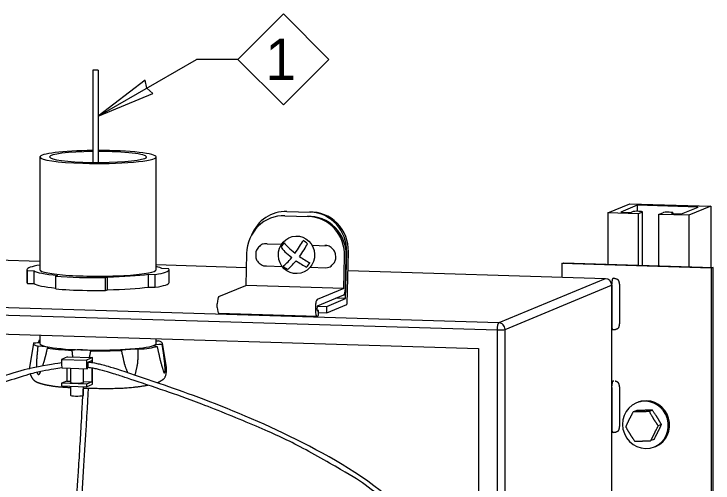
# Model space of a CAD drawing. Extents: x 99862 to 104211, y 98939 to 102076.
# Drawn here: x 102473.8 to 102744.3, y 101168.9 to 101350.4 of the extents above; entities that cross this region are included whole.
import ezdxf

# ---------------------------------------------------------------- set-up
doc = ezdxf.new("R2010")
doc.units = 0
for name, color, linetype in [('Level 1', 7, 'Continuous'), ('Level 11', 7, 'Continuous'), ('Level 15', 7, 'Continuous'), ('Level 17', 7, 'Continuous'), ('Level 18', 7, 'Continuous'), ('Level 19', 7, 'Continuous'), ('Level 20', 7, 'Continuous'), ('Level 22', 7, 'Continuous'), ('Level 30', 7, 'Continuous'), ('Level 4', 7, 'Continuous'), ('Level 5', 7, 'Continuous'), ('Level 6', 7, 'Continuous'), ('Level 8', 7, 'Continuous'), ('Level 9', 7, 'Continuous')]:
    doc.layers.add(name, color=color, linetype=linetype)

msp = doc.modelspace()

# ---------------------------------------------------------------- linework, layer by layer
at = {"layer": 'Level 1'}
for p, q in [((102483.78, 101254.68), (102435.76, 101256.14)), ((102563.61, 101252.25), (102528.78, 101253.31)), ((102702.71, 101248.01), (102602.99, 101251.05)), ((102702.63, 101248), (102661.4, 101230.93)), ((102663.81, 101228.38), (102705.04, 101245.44)), ((102705.04, 101245.44), (102705.04, 101150.38)), ((102661.4, 101230.93), (102318.77, 101241.36)), ((102318.11, 101238.61), (102660.74, 101228.18)), ((102325.59, 101230.93), (102653.5, 101220.95)), ((102660.74, 101228.18), (102660.74, 100794.54)), ((102663.81, 100794.74), (102663.81, 101228.38)), ((102653.5, 101220.95), (102653.5, 100802.46))]:
    msp.add_line(p, q, dxfattribs=at)
msp.add_arc((102702.63, 101245.51), 2.5, 360, 88.2563, dxfattribs=at)
for centre, major_axis, ratio, start_param, end_param in [((102702.63, 101245.51), (0.08, 2.5), 0.260126, 0, 0.1165), ((102702.63, 101245.51), (-2.5, 0), 0.112235, 2.876726, 3.141593), ((102661.4, 101228.45), (0.08, 2.5), 0.260126, 0.1165, 1.687296), ((102661.4, 101228.45), (0.96, -2.31), 0.959029, 1.163464, 2.734261), ((102661.4, 101228.45), (2.5, 0), 0.112235, 4.447522, 6.018319)]:
    msp.add_ellipse(centre, major_axis=major_axis, ratio=ratio, start_param=start_param, end_param=end_param, dxfattribs=at)
at = {"layer": 'Level 11'}
msp.add_ellipse((102583.09, 101257.22), major_axis=(0.3, -7.27), ratio=0.965403, dxfattribs=at)
for centre, major_axis, ratio, start_param, end_param in [((102582.66, 101257.2), (0.27, -6.47), 0.965403, 3.859694, 4.191654), ((102584.38, 101258.1), (6.19, -4.51), 0.165581, 3.52142, 4.536345), ((102581.75, 101258.92), (4.51, 6.19), 0.165581, 4.664043, 5.491937), ((102582.65, 101257.2), (6.47, 0.27), 0.965403, 0.715535, 1.047495), ((102583.14, 101256.39), (-6.19, 4.5), 0.165581, 0.380026, 1.385852), ((102583.46, 101257.68), (-4.5, -6.19), 0.165581, 1.520706, 2.350146), ((102584.38, 101258.1), (6.19, -4.51), 0.165581, 4.812672, 5.491937), ((102581.75, 101258.92), (4.51, 6.19), 0.165581, 3.52142, 4.383143), ((102583.46, 101257.68), (-4.5, -6.19), 0.165581, 0.380026, 1.239194), ((102583.14, 101256.39), (-6.19, 4.5), 0.165581, 1.662256, 2.350146), ((102582.66, 101257.2), (0.27, -6.47), 0.965403, 0.715535, 1.047495), ((102582.65, 101257.2), (6.47, 0.27), 0.965403, 3.859694, 4.191654)]:
    msp.add_ellipse(centre, major_axis=major_axis, ratio=ratio, start_param=start_param, end_param=end_param, dxfattribs=at)
at = {"layer": 'Level 15'}
for p in [(102506.28, 101310.85), (102560.45, 101332.88)]:
    msp.add_line(p, (102544.45, 101332.88), dxfattribs=at)
msp.add_lwpolyline([(102506.28, 101310.85), (102527.55, 101319.68), (102525.14, 101321.73), (102524.56, 101324.85)], close=True, dxfattribs=at)
at = {"layer": 'Level 17'}
for p, q in [((102703.63, 101273.48), (102712.14, 101277)), ((102715, 101276.44), (102708.62, 101273.8)), ((102712.14, 101277), (102743.51, 101276.05)), ((102715, 101276.44), (102715, 101274.07)), ((102738.52, 101275.73), (102715, 101276.44)), ((102732.14, 101273.09), (102738.52, 101275.73)), ((102743.51, 101276.05), (102735, 101272.53)), ((102743.51, 101276.05), (102743.51, 101252.39)), ((102703.63, 101273.48), (102703.63, 101253.61)), ((102715.4, 101273.12), (102703.63, 101273.48)), ((102708.62, 101273.8), (102712.54, 101273.68)), ((102712.54, 101273.68), (102713.07, 101273.9)), ((102716.99, 101273.79), (102715.4, 101273.12)), ((102715.4, 101273.12), (102715.4, 101253.25)), ((102715.55, 101274.06), (102715.58, 101274.06)), ((102717.07, 101253.2), (102717.07, 101273.84)), ((102723.24, 101272.88), (102724.84, 101273.55)), ((102723.24, 101272.88), (102723.24, 101253.01)), ((102735, 101272.53), (102723.24, 101272.88)), ((102728.76, 101273.43), (102728.22, 101273.21)), ((102728.22, 101273.21), (102732.14, 101273.09)), ((102728.83, 101273.19), (102728.83, 101273.49)), ((102735, 101272.53), (102735, 101252.65))]:
    msp.add_line(p, q, dxfattribs=at)
for centre, start_param, end_param in [((102715.02, 101273.85), 1.30593, 2.876726), ((102715.05, 101273.84), 0, 1.30593), ((102715.05, 101273.84), 6.018319, 6.283185), ((102726.78, 101273.49), 1.30593, 2.876726), ((102726.81, 101273.49), 6.283185, 7.589115), ((102726.81, 101273.49), 6.018319, 6.283185)]:
    msp.add_ellipse(centre, major_axis=(2.01, 0), ratio=0.112235, start_param=start_param, end_param=end_param, dxfattribs=at)
at = {"layer": 'Level 18'}
for p, q in [((102685.75, 101253.86), (102685.75, 101248.51)), ((102743.65, 101252.1), (102685.75, 101253.86)), ((102744.31, 101045.46), (102744.31, 101252.37))]:
    msp.add_line(p, q, dxfattribs=at)
msp.add_lwpolyline([(102685.75, 101253.86), (102686.4, 101254.13), (102744.31, 101252.37), (102743.65, 101252.1), (102743.65, 101045.48)], dxfattribs=at)
at = {"layer": 'Level 19'}
for p, q in [((102715.12, 101200.12), (102714.63, 101199.92)), ((102714.58, 101196.93), (102713.35, 101196.43)), ((102720.89, 101197.11), (102719.67, 101196.6)), ((102724.35, 101191.56), (102723.13, 101191.05)), ((102721.51, 101185.83), (102720.28, 101185.33)), ((102721.66, 101182.93), (102722.15, 101183.13))]:
    msp.add_line(p, q, dxfattribs=at)
for centre, start_param, end_param in [((102718.15, 101191.43), 3.141593, 6.283185), ((102718.15, 101191.43), 2.914664, 3.141593), ((102718.63, 101191.63), 2.914664, 3.141593), ((102718.15, 101191.43), 6.283185, 9.197849), ((102718.63, 101191.63), 6.283185, 9.197849)]:
    msp.add_ellipse(centre, major_axis=(3.52, -8.5), ratio=0.959029, start_param=start_param, end_param=end_param, dxfattribs=at)
for points in [[(102720.89, 101197.11), (102718.87, 101197.09), (102716.77, 101197.03), (102714.58, 101196.93)], [(102724.35, 101191.56), (102723.41, 101193.24), (102722.38, 101194.89), (102720.89, 101197.11)], [(102713.35, 101196.43), (102712.32, 101194.48), (102711.37, 101192.58), (102710.51, 101190.7)], [(102719.67, 101196.6), (102717.48, 101196.51), (102715.37, 101196.45), (102713.35, 101196.43)], [(102723.13, 101191.05), (102722.03, 101192.67), (102720.99, 101194.31), (102719.67, 101196.6)], [(102721.51, 101185.83), (102722.54, 101187.78), (102723.49, 101189.69), (102724.35, 101191.56)], [(102710.51, 101190.7), (102711.59, 101188.82), (102712.72, 101186.96), (102713.97, 101185.15)], [(102720.28, 101185.33), (102721.15, 101187.2), (102722.1, 101189.11), (102723.13, 101191.05)], [(102713.97, 101185.15), (102715.99, 101185.17), (102718.09, 101185.23), (102720.28, 101185.33)]]:
    msp.add_open_spline(points, degree=2, dxfattribs=at)
at = {"layer": 'Level 20'}
msp.add_lwpolyline([(102578.01, 101350.44), (102595.56, 101332.88), (102578.01, 101315.33), (102560.45, 101332.88)], close=True, dxfattribs=at)
at = {"layer": 'Level 22'}
for p, q in [((102705.1, 101245.47), (102705.1, 101230.32)), ((102708.1, 101245.88), (102708.1, 101230.49)), ((102705.56, 101228.32), (102705.86, 101228.28)), ((102705.72, 101208.45), (102705.7, 101208.45)), ((102705.72, 101208.45), (102705.87, 101208.44)), ((102705.1, 101205.95), (102705.1, 101190.57)), ((102708.1, 101206.13), (102708.1, 101190.75)), ((102705.63, 101188.56), (102705.84, 101188.55))]:
    msp.add_line(p, q, dxfattribs=at)
for points in [[(102705.86, 101228.28), (102706.05, 101228.29), (102706.56, 101228.39)], [(102705.84, 101188.55), (102706.03, 101188.56), (102706.54, 101188.66)]]:
    msp.add_lwpolyline(points, dxfattribs=at)
msp.add_ellipse((102705.83, 101208.46), major_axis=(0.129, 0), ratio=0.112235, start_param=3.805799, end_param=5.089246, dxfattribs=at)
for points in [[(102705.7, 101248.19), (102705.41, 101248.03), (102705.22, 101247.41), (102705.11, 101245.84)], [(102708.1, 101245.88), (102708.04, 101247.02), (102707.47, 101247.77), (102705.7, 101248.19)], [(102705.1, 101230.32), (102705.12, 101229.18), (102705.27, 101228.51), (102705.56, 101228.32)], [(102706.56, 101228.39), (102707.54, 101228.73), (102708.06, 101229.42), (102708.1, 101230.49)], [(102705.7, 101208.45), (102705.4, 101208.28), (102705.21, 101207.62), (102705.12, 101206.5)], [(102708.1, 101206.13), (102708.04, 101207.28), (102707.47, 101208.02), (102706.4, 101208.37)], [(102705.1, 101190.57), (102705.12, 101189.43), (102705.27, 101188.77), (102705.56, 101188.57)], [(102706.56, 101188.65), (102707.54, 101188.98), (102708.06, 101189.67), (102708.1, 101190.75)]]:
    msp.add_open_spline(points, degree=2, dxfattribs=at)
at = {"layer": 'Level 30'}
msp.add_line((102506.28, 101328.68), (102504.28, 101328.68), dxfattribs=at)
for points, degree in [([(102504.28, 101328.68), (102504.28, 101327.89), (102504.28, 101327.09), (102504.28, 101293.02)], 2), ([(102506.28, 101328.68), (102506.28, 101327.92), (102506.28, 101327.15), (102506.28, 101293.01)], 2), ([(102653.5, 101080.61), (102648.82, 101143.1), (102596.56, 101184.64), (102512.98, 101213.37), (102506.37, 101215.18), (102502.55, 101215.62), (102502.45, 101215.64)], 3), ([(102492.15, 101215.46), (102490.81, 101215.29), (102482.9, 101214.1), (102460.41, 101208.52), (102393.4, 101170.91), (102377.25, 101084.36), (102372.86, 101072.92), (102370.82, 101069.79), (102370.54, 101069.4)], 3), ([(102492.38, 101213.47), (102491.09, 101213.31), (102489.67, 101213.1), (102484.6, 101212.21), (102480.39, 101211.29), (102469.68, 101207.9), (102463.18, 101205.42), (102447.09, 101197.96), (102437.56, 101193), (102419.16, 101179.88), (102410.3, 101171.73), (102400.16, 101156.6), (102397.28, 101151.02), (102392.33, 101139.44), (102390.27, 101133.43), (102386.76, 101121.61), (102385.31, 101115.8), (102382.84, 101104.99), (102381.81, 101099.99), (102379.02, 101087.14), (102377.57, 101081.49), (102375.73, 101075.59), (102375.17, 101074.04), (102374.11, 101071.5), (102373.6, 101070.51), (102372.66, 101068.93), (102372.22, 101068.27), (102371.74, 101067.68)], 3), ([(102652.41, 101059.13), (102651.5, 101080.89), (102649.81, 101096.71), (102643.91, 101122.9), (102639.7, 101133.26), (102629.63, 101150.15), (102623.77, 101156.69), (102611.07, 101167.56), (102604.24, 101171.89), (102583.43, 101183.84), (102569.35, 101190.28), (102544.15, 101200.52), (102533.03, 101204.31), (102517.07, 101209.68), (102512.28, 101211.24), (102507.45, 101212.64), (102506.24, 101212.95), (102504.21, 101213.38), (102503.39, 101213.51), (102502.46, 101213.62), (102502.41, 101213.63), (102502.36, 101213.63)], 3), ([(102502.44, 101205.65), (102501.86, 101194.2), (102498.75, 101142.75), (102493.68, 101073.03), (102493.68, 101042.56), (102502.95, 101036.94), (102508.51, 101035.84)], 3), ([(102500.29, 101202.72), (102499.91, 101195.44), (102499.52, 101188.73), (102498.94, 101179.16), (102498.75, 101176.05), (102498.36, 101169.93), (102497.79, 101160.9), (102497.24, 101152.33), (102495.44, 101124.86), (102494.17, 101106.31), (102493.07, 101087.93), (102492.88, 101084.5), (102492.55, 101078.11), (102492.41, 101075.16), (102492.11, 101066.96), (102492.05, 101062.36), (102492.32, 101054.5), (102492.66, 101051.24), (102493.58, 101047.04), (102493.96, 101045.76), (102494.89, 101043.4), (102495.44, 101042.31), (102497.35, 101039.36), (102498.96, 101037.8), (102502.69, 101035.44), (102504.79, 101034.64), (102507.43, 101034.02), (102507.8, 101033.94), (102508.18, 101033.86)], 3)]:
    msp.add_open_spline(points, degree=degree, dxfattribs=at)
at = {"layer": 'Level 4'}
for p, q in [((102483.78, 101295.11), (102483.78, 101251.49)), ((102528.78, 101251.49), (102528.78, 101295.11)), ((102478.78, 101251.49), (102478.78, 101246.52)), ((102478.94, 101251.16), (102481.55, 101251.08)), ((102478.94, 101246.19), (102478.94, 101251.16)), ((102481.55, 101246.11), (102481.55, 101251.08)), ((102533.63, 101251.82), (102531.02, 101251.9)), ((102533.78, 101246.52), (102533.78, 101251.49)), ((102490.63, 101249.3), (102489.93, 101249.01)), ((102489.93, 101244.04), (102489.93, 101249.01)), ((102509.23, 101248.42), (102509.94, 101248.71)), ((102509.23, 101243.45), (102509.23, 101248.42)), ((102509.94, 101243.75), (102509.94, 101248.71)), ((102525.78, 101249.73), (102528.39, 101249.65)), ((102525.78, 101244.77), (102525.78, 101249.73)), ((102528.39, 101244.69), (102528.39, 101249.65)), ((102478.94, 101246.19), (102481.55, 101246.11)), ((102509.23, 101243.45), (102509.94, 101243.75)), ((102525.78, 101244.77), (102528.39, 101244.69)), ((102483.78, 101226.11), (102483.78, 101222.89)), ((102528.78, 101222.89), (102528.78, 101224.74))]:
    msp.add_line(p, q, dxfattribs=at)
for centre, major_axis, start_param, end_param in [((102506.28, 101295.11), (22.5, 0), 1.659816, 3.141593), ((102506.28, 101295.11), (-18.75, 0), 4.819275, 6.283185), ((102506.28, 101295.11), (22.5, 0), 0, 1.570808), ((102506.28, 101295.11), (-18.75, 0), 3.141593, 4.712403), ((102506.28, 101295.11), (22.5, 0), 3.141593, 4.447522), ((102506.28, 101295.11), (-18.75, 0), 6.283185, 9.159911), ((102506.28, 101295.11), (22.5, 0), 4.447522, 6.283185), ((102506.28, 101295.11), (-18.75, 0), 2.876726, 3.141593), ((102506.28, 101251.49), (-27.5, 0), 5.670631, 6.283185), ((102506.28, 101251.49), (-27.5, 0), 0, 0.107302), ((102506.28, 101251.49), (-25, 0), 0.14665, 0.894413), ((102506.28, 101251.49), (-22.5, 0), 0, 3.141593), ((102506.28, 101251.49), (-27.5, 0), 2.504558, 3.141593), ((102506.28, 101251.49), (-25, 0), 3.288243, 3.592619), ((102506.28, 101251.49), (-27.5, 0), 3.141593, 3.248895), ((102506.28, 101251.49), (-27.5, 0), 0.933761, 1.678098), ((102506.28, 101251.49), (-25, 0), 1.717447, 2.465209), ((102506.28, 101246.52), (-27.5, 0), 0, 0.107302), ((102506.28, 101246.52), (-25, 0), 0.14665, 0.857545), ((102506.28, 101246.52), (-27.5, 0), 2.504558, 3.141593), ((102506.28, 101246.52), (-27.5, 0), 0.933761, 1.155187), ((102506.28, 101246.52), (-27.5, 0), 1.155187, 1.678098), ((102506.28, 101246.52), (-25, 0), 1.717447, 2.465209), ((102506.28, 101222.89), (22.5, 0), 3.141593, 4.712389), ((102506.28, 101222.89), (22.5, 0), 4.712389, 6.283185)]:
    msp.add_ellipse(centre, major_axis=major_axis, ratio=0.112235, start_param=start_param, end_param=end_param, dxfattribs=at)
at = {"layer": 'Level 5'}
for p, q in [((102483.43, 101224.03), (102483.29, 101223.38)), ((102481.29, 101222.94), (102479.76, 101213.83)), ((102532.81, 101213.83), (102531.28, 101222.94)), ((102484.86, 101214.24), (102485.04, 101214.71)), ((102483.86, 101211.53), (102484.04, 101212.02))]:
    msp.add_line(p, q, dxfattribs=at)
msp.add_lwpolyline([(102531.39, 101212.81), (102531.53, 101212.4), (102531.53, 101212.39)], dxfattribs=at)
for centre, major_axis, ratio, start_param, end_param in [((102506.28, 101222.89), (-25, 0), 0.112235, 5.832158, 5.865849), ((102479.1, 101223.72), (5.29, -0.02), 0.106412, 0.484477, 0.612936), ((102530.72, 101224.46), (-5.24, -0.03), 0.108666, 1.191344, 1.356306), ((102506.28, 101222.89), (-25, 0), 0.112235, 3.160419, 3.509654), ((102506.28, 101222.89), (-25, 0), 0.112235, 6.264359, 6.651247), ((102506.28, 101222.89), (-25, 0), 0.112235, 6.170789, 6.264359), ((102479.1, 101223.72), (5.29, -0.02), 0.106412, 5.171338, 5.799417), ((102481.85, 101221.32), (5.24, 0.03), 0.108666, 6.248955, 7.639491), ((102481.85, 101221.32), (5.24, 0.03), 0.108666, 5.914708, 6.248955), ((102506.28, 101222.89), (-25, 0), 0.112235, 0.673002, 1.15346), ((102506.28, 101222.89), (-25, 0), 0.112235, 2.243798, 2.724256), ((102533.47, 101222.06), (-5.29, 0.02), 0.106412, 5.171338, 6.320463), ((102533.47, 101222.06), (-5.29, 0.02), 0.106412, 0.037278, 0.612936), ((102506.28, 101222.89), (-25, 0), 0.112235, 3.029196, 3.160419), ((102498.91, 101219.84), (-5.02, -0.02), 0.11826, 3.56882, 5.293603), ((102506.28, 101222.89), (-25, 0), 0.112235, 1.4584, 1.938858), ((102520.29, 101220.15), (-5.08, 0.03), 0.11559, 4.398046, 6.122829), ((102506.28, 101208.32), (23.4, 0), 0.112235, 3.465018, 3.516191)]:
    msp.add_ellipse(centre, major_axis=major_axis, ratio=ratio, start_param=start_param, end_param=end_param, dxfattribs=at)
for points in [[(102482.96, 101221.88), (102482.74, 101219.15), (102482.46, 101216.39), (102482.45, 101213.71)], [(102485.04, 101214.71), (102485.68, 101216.81), (102486.22, 101218.97), (102486.73, 101221.14)], [(102529.14, 101221.75), (102529.84, 101218.72), (102530.53, 101215.6), (102531.39, 101212.81)], [(102532.29, 101213.03), (102532.02, 101216.25), (102531.6, 101219.41), (102531.13, 101222.58)], [(102496.15, 101220.33), (102496.24, 101219.46), (102496.33, 101218.58), (102496.42, 101217.71)], [(102502.99, 101217.51), (102503.17, 101218.37), (102503.33, 101219.24), (102503.48, 101220.1)], [(102515.28, 101220.27), (102515.98, 101217.32), (102516.59, 101214.3), (102517.8, 101211.52)], [(102520.59, 101210.62), (102521.6, 101214.34), (102521.82, 101217.51), (102521.87, 101220.7)], [(102479.76, 101213.85), (102479.71, 101213.57), (102479.68, 101213.29), (102479.67, 101213.02)], [(102529.15, 101207.72), (102530.66, 101208.38), (102532.84, 101210.13), (102532.81, 101213.83)], [(102531.53, 101212.39), (102531.77, 101211.39), (102532.28, 101211.78), (102532.29, 101213.03)], [(102480.05, 101211.05), (102480.86, 101209.08), (102482.82, 101207.79), (102484.09, 101207.49)], [(102482.64, 101211.7), (102482.93, 101211.05), (102483.53, 101210.87), (102483.86, 101211.53)], [(102520.57, 101210.6), (102520.58, 101210.61), (102520.58, 101210.62), (102520.59, 101210.62)], [(102484.5, 101207.36), (102485.29, 101207.14), (102485.98, 101206.97), (102486.8, 101206.83)], [(102486.8, 101206.83), (102488.99, 101206.41), (102492.1, 101206.1), (102495.65, 101205.9)], [(102500.65, 101205.69), (102509.61, 101205.46), (102519.83, 101205.81), (102525.6, 101206.81)]]:
    msp.add_open_spline(points, degree=2, dxfattribs=at)
at = {"layer": 'Level 6'}
for p, q in [((102579.42, 101274.03), (102588.43, 101273.76)), ((102602.06, 101240.31), (102602.52, 101258.32)), ((102602.66, 101238.3), (102603.18, 101258.35)), ((102594.8, 101237.3), (102602.06, 101240.31)), ((102602.06, 101240.31), (102598.32, 101240.42)), ((102591.16, 101237.41), (102594.8, 101237.3)), ((102594.8, 101234.82), (102602.6, 101238.05)), ((102594.8, 101234.82), (102594.8, 101237.3)), ((102591.64, 101234.92), (102594.8, 101234.82))]:
    msp.add_line(p, q, dxfattribs=at)
for centre, major_axis, ratio, start_param, end_param in [((102579.03, 101259.04), (0.63, -14.99), 0.965403, 3.07178, 4.270302), ((102588.7, 101258.79), (0.63, -14.99), 0.965403, 1.500987, 3.141593), ((102588.05, 101258.77), (0.63, -14.99), 0.965403, 1.500987, 3.071783), ((102602.6, 101238.3), (0.008, 0.25), 0.260126, 3.258092, 4.731227)]:
    msp.add_ellipse(centre, major_axis=major_axis, ratio=ratio, start_param=start_param, end_param=end_param, dxfattribs=at)
at = {"layer": 'Level 8'}
for p, q in [((102494.5, 101217.77), (102492.15, 101216.8)), ((102492.15, 101216.8), (102492.15, 101214.56)), ((102492.15, 101216.8), (102501.8, 101216.5)), ((102494.5, 101217.77), (102504.15, 101217.48)), ((102504.15, 101217.48), (102501.8, 101216.5)), ((102501.8, 101216.5), (102501.8, 101214.27)), ((102502.45, 101215.74), (102503.91, 101216.35)), ((102502.45, 101214.54), (102502.45, 101215.74)), ((102503.91, 101216.35), (102503.91, 101215.44)), ((102504.15, 101215.4), (102504.15, 101217.48)), ((102492.44, 101213.45), (102502.09, 101213.16)), ((102494.26, 101213.39), (102494.26, 101208.41)), ((102495.65, 101213.35), (102495.65, 101207.87)), ((102500.65, 101207.87), (102500.65, 101213.2)), ((102503.91, 101213.42), (102503.91, 101208.11)), ((102504.15, 101207.18), (102504.15, 101213.38)), ((102494.26, 101208.41), (102492.15, 101207.53)), ((102492.15, 101207.53), (102492.15, 101206.5)), ((102501.8, 101207.24), (102492.15, 101207.53)), ((102494.26, 101208.41), (102495.65, 101208.36)), ((102500.65, 101208.21), (102503.91, 101208.11)), ((102503.91, 101208.11), (102501.8, 101207.24)), ((102492.15, 101206.5), (102501.8, 101206.21)), ((102495.65, 101206.39), (102495.65, 101202.87)), ((102500.41, 101205.23), (102500.41, 101202.75)), ((102500.64, 101202.84), (102500.64, 101205.33)), ((102500.65, 101202.87), (102500.65, 101206.24)), ((102501.8, 101207.24), (102501.8, 101206.21)), ((102501.8, 101206.21), (102504.15, 101207.18)), ((102500.41, 101202.85), (102500.64, 101202.84))]:
    msp.add_line(p, q, dxfattribs=at)
for centre, major_axis, ratio, start_param, end_param in [((102492.47, 101214.7), (0.04, 1.25), 0.260126, 1.687296, 3.141593), ((102502.13, 101214.4), (0.04, 1.25), 0.260126, 1.687296, 3.141593), ((102502.13, 101214.4), (0.04, 1.25), 0.260126, 3.141593, 4.828889), ((102498.15, 101207.87), (-2.5, 0), 0.112235, 0, 1.30593), ((102498.15, 101207.87), (-2.5, 0), 0.112235, 1.30593, 3.141593), ((102498.15, 101205.35), (-2.5, 0), 0.112235, 2.699419, 3.054033), ((102498.15, 101202.87), (-2.5, 0), 0.112235, 0, 2.699419), ((102498.15, 101202.87), (-2.5, 0), 0.112235, 3.054033, 3.141593)]:
    msp.add_ellipse(centre, major_axis=major_axis, ratio=ratio, start_param=start_param, end_param=end_param, dxfattribs=at)
at = {"layer": 'Level 9'}
for p, q in [((102578.61, 101272.36), (102587.63, 101272.09)), ((102571.69, 101261.48), (102577.26, 101261.31)), ((102589.11, 101260.95), (102594.64, 101260.78)), ((102563.75, 101257.81), (102563.43, 101245.34)), ((102601.4, 101244.18), (102601.72, 101256.65)), ((102602.05, 101244.21), (102602.37, 101256.68)), ((102571.5, 101252.94), (102577.54, 101252.76)), ((102588.39, 101252.43), (102594.45, 101252.24)), ((102553.09, 101241.06), (102563.43, 101245.34)), ((102601.4, 101244.18), (102563.43, 101245.34)), ((102601.4, 101244.18), (102591.06, 101239.9)), ((102591.23, 101237.49), (102601.4, 101241.7)), ((102552.44, 101236.91), (102552.44, 101238.3)), ((102552.91, 101234.69), (102591.06, 101233.53)), ((102590.41, 101237.15), (102590.41, 101235.76)), ((102590.97, 101236.37), (102590.97, 101236.39)), ((102591.64, 101235.65), (102591.06, 101235.67)), ((102591.23, 101235.49), (102591.17, 101235.49)), ((102591.64, 101235.65), (102591.23, 101235.49)), ((102591.64, 101233.78), (102591.64, 101235.65)), ((102591.06, 101233.54), (102591.64, 101233.78))]:
    msp.add_line(p, q, dxfattribs=at)
for centre, major_axis, ratio, start_param, end_param in [((102578.23, 101257.37), (0.63, -14.99), 0.965403, 3.071783, 4.64258), ((102587.9, 101257.12), (0.63, -14.99), 0.965403, 1.500987, 3.141593), ((102587.24, 101257.09), (0.63, -14.99), 0.965403, 1.500987, 3.071787), ((102601.4, 101244.18), (-0.08, -2.5), 0.260126, 0.1165, 1.589635), ((102553.09, 101238.57), (0.08, 2.5), 0.260126, 0.1165, 1.687296), ((102591.06, 101237.42), (-0.08, -2.5), 0.260126, 3.258092, 4.828889), ((102591.23, 101236.5), (0.03, 1), 0.260126, 0.1165, 1.687296), ((102553.09, 101237.18), (0.08, 2.5), 0.260126, 1.687296, 3.141593), ((102591.06, 101236.03), (-0.08, -2.5), 0.260126, 4.828889, 6.283185), ((102591.23, 101236.48), (0.03, 1), 0.260126, 1.687296, 3.141593), ((102591.23, 101236.48), (0.03, 1), 0.260126, 3.141593, 3.258092), ((102591.06, 101236.03), (-0.08, -2.5), 0.260126, 0, 0.1165)]:
    msp.add_ellipse(centre, major_axis=major_axis, ratio=ratio, start_param=start_param, end_param=end_param, dxfattribs=at)
for points in [[(102571.69, 101261.48), (102571.51, 101261.5), (102571.33, 101261.51), (102570.1, 101261.46), (102569.11, 101260.99), (102567.65, 101259.34), (102567.24, 101258.22), (102567.34, 101255.89), (102567.84, 101254.8), (102569.44, 101253.28), (102570.46, 101252.9), (102571.5, 101252.94)], [(102594.45, 101252.24), (102595.49, 101252.29), (102596.47, 101252.75), (102597.94, 101254.4), (102598.34, 101255.53), (102598.25, 101257.85), (102597.75, 101258.94), (102596.15, 101260.46), (102595.13, 101260.84), (102594.09, 101260.8)]]:
    msp.add_open_spline(points, degree=3, dxfattribs=at)

# ---------------------------------------------------------------- texts
at = {"layer": 'Level 20'}
msp.add_text('1', height=16, dxfattribs=at).set_placement((102571.05, 101324.89))

doc.saveas('drawing.dxf')
